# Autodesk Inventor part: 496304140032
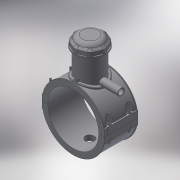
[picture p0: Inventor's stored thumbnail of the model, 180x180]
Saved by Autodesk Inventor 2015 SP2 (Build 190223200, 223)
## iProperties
Created: 2017-07
Part Number: 496304140032
Material: Generic
Description: PLASSON TAPPING SADDLE 140x32
Document SubType Name: Modeling
Designer: KIM
Mass: 922.45 g
Surface Area: 2213.14 cm^2
Volume: 922.45 cm^3
Density: 1 g/cm^3
Appearance: Default
Author: KIM
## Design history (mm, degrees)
derived "496304.ipt"
feature "Solid1::496304.ipt"
feature "Solid2::496304.ipt"
feature "Solid4::496304.ipt"
feature "Solid5::496304.ipt"
tag "TaggingFeature1"
body "Solid1"
body "Solid2"
other parameters: "d3" = 35, "d4" = 118, "d5" = 0, "d6" = 0.1, "d8" = 0, "d19" = 6, "d20" = 6, "d21" = 70.8, "d23" = 0, "d24" = 35.4, "d26" = 0, "d29" = 3, "d30" = 46.66667, "d31" = 6, "d32" = 0, "d33" = 0, "d34" = 0.6, "d40" = 82.992, "d43" = 0, "d45" = 0, "d47" = 150.6, "d70" = 15, "d72" = 0, "d73" = 6, "d75" = 5, "d76" = 0, "d77" = 7, "d79" = 15, "d80" = 47.2, "d82" = 5 deg, "d84" = 4, "d85" = 14, "d86" = 0, "d87" = 3, "d88" = 0, "d89" = 1, "d90" = 1, "d91" = 94.4, "d92" = 0, "d93" = 0.5, "d94" = 73.68421, "d96" = 162.792, "d97" = 2.36, "d98" = 0, "d102" = 1.4, "d120" = 140 deg, "d121" = 24.228, "d122" = 20 deg, "d123" = 319.2, "d124" = 95.76, "d126" = 0, "d143" = 144.2, "d145" = 15.07692, "d149" = 2.1, "d150" = 16.58462, "d153" = 118, "d154" = 0, "d156" = 79.8, "d157" = 160 deg, "d159" = 3.92, "d161" = 2.1, "d162" = 70.8, "d163" = 0, "d167" = 14, "d168" = 77.85366, "d170" = 3.375, "d172" = 0, "d173" = 1, "d176" = 20 deg, "d177" = 9.8, "d178" = 19.6, "d180" = 0, "d183" = 7.84, "d184" = 7.84, "d185" = 38.35, "d186" = 38.35, "d187" = 79.8, "d188" = 5.88, "d189" = 9.8, "d190" = 0, "d191" = 119.7, "d193" = 6.3, "d194" = 4.13, "d195" = 90 deg, "d197" = 0, "d199" = 0, "d200" = 9.8, "d202" = 0, "d203" = 177, "d204" = 66.5, "d205" = 49, "d206" = 59.5, "d207" = 132.75, "d208" = 138.06, "d209" = 164.61, "d210" = 60.2, "d212" = 56, "d213" = 36, "d216" = 0, "d217" = 14, "d218" = 14, "d219" = 2.8, "d224" = 0, "d230" = 5.6, "d233" = 6, "d237" = 35.4, "d238" = 6.02433, "d240" = 35.4, "d241" = 35.4, "d242" = 35.4, "d243" = 6, "d244" = 35.4, "d245" = 35.4, "d246" = 35.4, "d247" = 6, "d248" = 6, "d249" = 6, "d251" = 35.4, "d253" = 6, "d254" = 6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
